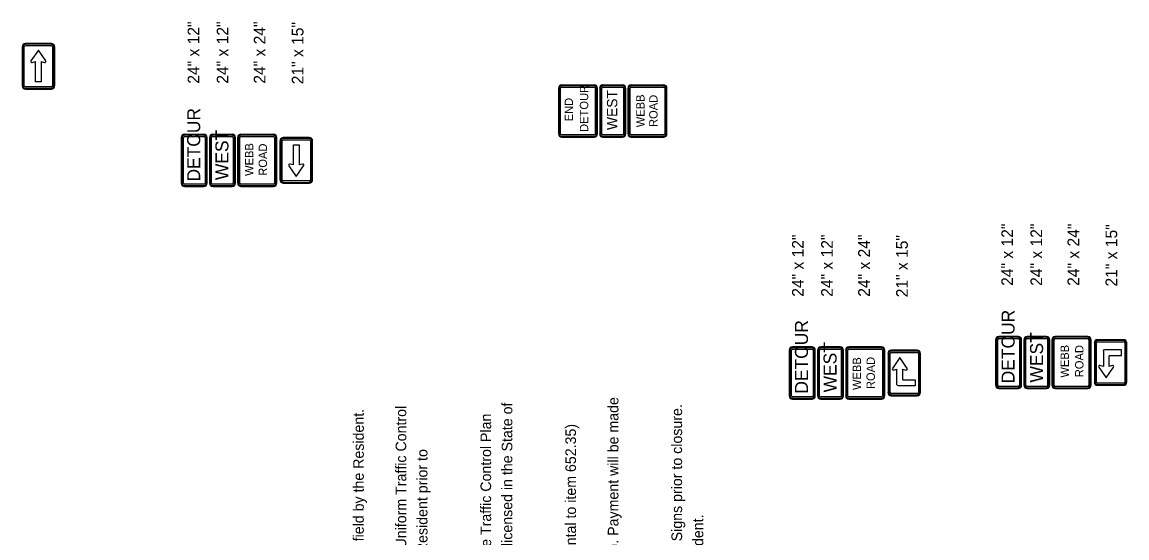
# Model space of a CAD drawing. Extents: x 1123038 to 1172987, y 554419 to 623636.
# Drawn here: x 1160796 to 1172459, y 569560 to 575008 of the extents above; entities that cross this region are included whole.
import ezdxf

# ---------------------------------------------------------------- set-up
doc = ezdxf.new("R2010")
doc.units = 0
doc.layers.add('D_Text_Standard', color=7, linetype='Continuous')
doc.layers.add('Default', color=7, linetype='Continuous')

msp = doc.modelspace()

# ---------------------------------------------------------------- linework, layer by layer
at = {"layer": 'Default'}
for p, q in [((1161105, 574782), (1160830, 574782)), ((1161105, 574773), (1160830, 574773)), ((1160830, 574759), (1161105, 574759)), ((1160796, 574747), (1160796, 574335)), ((1160804, 574747), (1160804, 574335)), ((1160819, 574335), (1160819, 574747)), ((1160968, 574713), (1160889, 574599)), ((1161046, 574599), (1160968, 574713)), ((1161117, 574747), (1161117, 574335)), ((1161131, 574335), (1161131, 574747)), ((1161140, 574335), (1161140, 574747)), ((1160901, 574581), (1160938, 574590)), ((1160938, 574378), (1160938, 574590)), ((1160998, 574590), (1161034, 574581)), ((1160998, 574590), (1160998, 574378)), ((1161105, 574323), (1160830, 574323)), ((1160830, 574309), (1161105, 574309)), ((1160830, 574300), (1161105, 574300)), ((1160998, 574378), (1160938, 574378)), ((1166457, 574309), (1166457, 573827)), ((1166466, 574309), (1166466, 573827)), ((1166480, 573827), (1166480, 574309)), ((1166836, 574343), (1166492, 574343)), ((1166836, 574334), (1166492, 574334)), ((1166492, 574320), (1166836, 574320)), ((1166847, 574309), (1166847, 573827)), ((1166861, 573827), (1166861, 574309)), ((1166870, 573827), (1166870, 574309)), ((1166893, 574309), (1166893, 573827)), ((1166901, 574309), (1166901, 573827)), ((1166916, 573827), (1166916, 574309)), ((1167133, 574343), (1166927, 574343)), ((1167133, 574334), (1166927, 574334)), ((1166927, 574320), (1167133, 574320)), ((1167145, 574309), (1167145, 573827)), ((1167159, 573827), (1167159, 574309)), ((1167168, 573827), (1167168, 574309)), ((1167191, 574309), (1167191, 573827)), ((1167199, 574309), (1167199, 573827)), ((1167214, 573827), (1167214, 574309)), ((1167569, 574343), (1167225, 574343)), ((1167569, 574334), (1167225, 574334)), ((1167225, 574320), (1167569, 574320)), ((1167580, 574309), (1167580, 573827)), ((1167595, 573827), (1167595, 574309)), ((1167603, 573827), (1167603, 574309)), ((1162716, 573822), (1162510, 573822)), ((1163014, 573822), (1162808, 573822)), ((1163449, 573822), (1163106, 573822)), ((1162475, 573788), (1162475, 573307)), ((1162484, 573788), (1162484, 573307)), ((1162498, 573307), (1162498, 573788)), ((1162716, 573814), (1162510, 573814)), ((1162510, 573800), (1162716, 573800)), ((1162728, 573788), (1162728, 573307)), ((1162742, 573307), (1162742, 573788)), ((1162750, 573307), (1162750, 573788)), ((1162773, 573788), (1162773, 573307)), ((1162782, 573788), (1162782, 573307)), ((1162796, 573307), (1162796, 573788)), ((1163014, 573814), (1162808, 573814)), ((1162808, 573800), (1163014, 573800)), ((1163025, 573788), (1163025, 573307)), ((1163040, 573307), (1163040, 573788)), ((1163048, 573307), (1163048, 573788)), ((1163071, 573788), (1163071, 573307)), ((1163080, 573788), (1163080, 573307)), ((1163094, 573307), (1163094, 573788)), ((1163449, 573814), (1163106, 573814)), ((1163106, 573800), (1163449, 573800)), ((1163461, 573788), (1163461, 573307)), ((1163475, 573307), (1163475, 573788)), ((1163484, 573307), (1163484, 573788)), ((1163518, 573754), (1163518, 573341)), ((1163527, 573754), (1163527, 573341)), ((1163541, 573341), (1163541, 573754)), ((1163828, 573788), (1163553, 573788)), ((1163828, 573779), (1163553, 573779)), ((1163553, 573765), (1163828, 573765)), ((1163660, 573711), (1163720, 573711)), ((1163660, 573499), (1163660, 573711)), ((1163720, 573711), (1163720, 573499)), ((1163839, 573754), (1163839, 573341)), ((1163853, 573341), (1163853, 573754)), ((1163862, 573341), (1163862, 573754)), ((1166836, 573816), (1166492, 573816)), ((1166492, 573802), (1166836, 573802)), ((1166492, 573793), (1166836, 573793)), ((1167133, 573816), (1166927, 573816)), ((1166927, 573802), (1167133, 573802)), ((1166927, 573793), (1167133, 573793)), ((1167569, 573816), (1167225, 573816)), ((1167225, 573802), (1167569, 573802)), ((1167225, 573793), (1167569, 573793)), ((1163612, 573490), (1163690, 573376)), ((1163660, 573499), (1163624, 573507)), ((1163690, 573376), (1163768, 573490)), ((1163756, 573507), (1163720, 573499)), ((1162716, 573295), (1162510, 573295)), ((1162510, 573281), (1162716, 573281)), ((1162510, 573272), (1162716, 573272)), ((1163014, 573295), (1162808, 573295)), ((1162808, 573281), (1163014, 573281)), ((1162808, 573272), (1163014, 573272)), ((1163449, 573295), (1163106, 573295)), ((1163106, 573281), (1163449, 573281)), ((1163106, 573272), (1163449, 573272)), ((1163828, 573330), (1163553, 573330)), ((1163553, 573315), (1163828, 573315)), ((1163553, 573307), (1163828, 573307)), ((1171072, 571653), (1171072, 571172)), ((1171081, 571653), (1171081, 571172)), ((1171095, 571172), (1171095, 571653)), ((1171313, 571687), (1171107, 571687)), ((1171313, 571679), (1171107, 571679)), ((1171107, 571665), (1171313, 571665)), ((1171324, 571653), (1171324, 571172)), ((1171339, 571172), (1171339, 571653)), ((1171347, 571172), (1171347, 571653)), ((1171370, 571653), (1171370, 571172)), ((1171379, 571653), (1171379, 571172)), ((1171393, 571172), (1171393, 571653)), ((1171611, 571687), (1171405, 571687)), ((1171611, 571679), (1171405, 571679)), ((1171405, 571665), (1171611, 571665)), ((1171622, 571653), (1171622, 571172)), ((1171637, 571172), (1171637, 571653)), ((1171645, 571172), (1171645, 571653)), ((1171668, 571653), (1171668, 571172)), ((1171677, 571653), (1171677, 571172)), ((1171691, 571172), (1171691, 571653)), ((1172046, 571687), (1171702, 571687)), ((1172046, 571679), (1171702, 571679)), ((1171702, 571665), (1172046, 571665)), ((1172058, 571653), (1172058, 571172)), ((1172072, 571172), (1172072, 571653)), ((1172081, 571172), (1172081, 571653)), ((1172115, 571619), (1172115, 571206)), ((1172124, 571619), (1172124, 571206)), ((1172138, 571206), (1172138, 571619)), ((1172424, 571653), (1172149, 571653)), ((1172424, 571645), (1172149, 571645)), ((1172149, 571630), (1172424, 571630)), ((1172436, 571619), (1172436, 571206)), ((1172450, 571206), (1172450, 571619)), ((1172459, 571206), (1172459, 571619)), ((1168894, 571542), (1168894, 571061)), ((1168903, 571542), (1168903, 571061)), ((1168917, 571061), (1168917, 571542)), ((1169135, 571577), (1168928, 571577)), ((1169135, 571568), (1168928, 571568)), ((1168928, 571554), (1169135, 571554)), ((1169146, 571542), (1169146, 571061)), ((1169160, 571061), (1169160, 571542)), ((1169169, 571061), (1169169, 571542)), ((1169192, 571542), (1169192, 571061)), ((1169200, 571542), (1169200, 571061)), ((1169215, 571061), (1169215, 571542)), ((1169433, 571577), (1169226, 571577)), ((1169433, 571568), (1169226, 571568)), ((1169226, 571554), (1169433, 571554)), ((1169444, 571542), (1169444, 571061)), ((1169458, 571061), (1169458, 571542)), ((1169467, 571061), (1169467, 571542)), ((1169490, 571542), (1169490, 571061)), ((1169498, 571542), (1169498, 571061)), ((1169513, 571061), (1169513, 571542)), ((1169868, 571577), (1169524, 571577)), ((1169868, 571568), (1169524, 571568)), ((1169524, 571554), (1169868, 571554)), ((1169879, 571542), (1169879, 571061)), ((1169894, 571061), (1169894, 571542)), ((1169902, 571061), (1169902, 571542)), ((1169937, 571508), (1169937, 571095)), ((1169945, 571508), (1169945, 571095)), ((1169960, 571095), (1169960, 571508)), ((1170246, 571542), (1169971, 571542)), ((1170246, 571534), (1169971, 571534)), ((1169971, 571519), (1170246, 571519)), ((1170258, 571508), (1170258, 571095)), ((1170272, 571095), (1170272, 571508)), ((1170280, 571095), (1170280, 571508)), ((1172210, 571533), (1172210, 571372)), ((1172403, 571546), (1172222, 571546)), ((1172278, 571486), (1172403, 571486)), ((1172403, 571486), (1172403, 571546)), ((1170061, 571465), (1169983, 571351)), ((1170140, 571351), (1170061, 571465)), ((1172210, 571372), (1172173, 571381)), ((1172270, 571372), (1172270, 571477)), ((1172306, 571381), (1172270, 571372)), ((1169995, 571333), (1170031, 571342)), ((1170031, 571181), (1170031, 571342)), ((1170091, 571342), (1170127, 571333)), ((1170091, 571342), (1170091, 571237)), ((1172161, 571363), (1172240, 571249)), ((1172240, 571249), (1172318, 571363)), ((1170225, 571168), (1170044, 571168)), ((1170100, 571229), (1170225, 571229)), ((1170225, 571229), (1170225, 571168)), ((1171313, 571160), (1171107, 571160)), ((1171107, 571146), (1171313, 571146)), ((1171107, 571137), (1171313, 571137)), ((1171611, 571160), (1171405, 571160)), ((1171405, 571146), (1171611, 571146)), ((1171405, 571137), (1171611, 571137)), ((1172046, 571160), (1171702, 571160)), ((1171702, 571146), (1172046, 571146)), ((1171702, 571137), (1172046, 571137)), ((1172424, 571195), (1172149, 571195)), ((1172149, 571180), (1172424, 571180)), ((1172149, 571172), (1172424, 571172)), ((1169135, 571050), (1168928, 571050)), ((1168928, 571035), (1169135, 571035)), ((1168928, 571027), (1169135, 571027)), ((1169433, 571050), (1169226, 571050)), ((1169226, 571035), (1169433, 571035)), ((1169226, 571027), (1169433, 571027)), ((1169868, 571050), (1169524, 571050)), ((1169524, 571035), (1169868, 571035)), ((1169524, 571027), (1169868, 571027)), ((1170246, 571084), (1169971, 571084)), ((1169971, 571070), (1170246, 571070)), ((1169971, 571061), (1170246, 571061))]:
    msp.add_line(p, q, dxfattribs=at)
for centre, radius, start, end in [((1160830, 574747), 34.4, 90, 180), ((1160830, 574747), 25.8, 90, 180), ((1160830, 574747), 11.5, 90, 180), ((1161105, 574747), 34.4, 0, 90), ((1161105, 574747), 25.8, 0, 90), ((1161105, 574747), 11.5, 0, 90), ((1160899, 574593), 11.5, 147.7244, 282.9503), ((1161036, 574593), 11.5, 257.0497, 32.2757), ((1160830, 574335), 34.4, 180, 270), ((1160830, 574335), 25.8, 180, 270), ((1160830, 574335), 11.5, 180, 270), ((1161105, 574335), 34.4, 270, 0), ((1161105, 574335), 25.8, 270, 0), ((1161105, 574335), 11.5, 270, 0), ((1166492, 574309), 34.4, 90, 180), ((1166492, 574309), 25.8, 90, 180), ((1166492, 574309), 11.5, 90, 180), ((1166836, 574309), 34.4, 0, 90), ((1166836, 574309), 25.8, 0, 90), ((1166836, 574309), 11.5, 0, 90), ((1166927, 574309), 34.4, 90, 180), ((1166927, 574309), 25.8, 90, 180), ((1166927, 574309), 11.5, 90, 180), ((1167133, 574309), 34.4, 0, 90), ((1167133, 574309), 25.8, 0, 90), ((1167133, 574309), 11.5, 0, 90), ((1167225, 574309), 34.4, 90, 180), ((1167225, 574309), 25.8, 90, 180), ((1167225, 574309), 11.5, 90, 180), ((1167569, 574309), 34.4, 0, 90), ((1167569, 574309), 25.8, 0, 90), ((1167569, 574309), 11.5, 0, 90), ((1162510, 573788), 34.4, 90, 180), ((1162716, 573788), 34.4, 0, 90), ((1162808, 573788), 34.4, 90, 180), ((1163014, 573788), 34.4, 0, 90), ((1163106, 573788), 34.4, 90, 180), ((1163449, 573788), 34.4, 0, 90), ((1166492, 573827), 34.4, 180, 270), ((1166492, 573827), 25.8, 180, 270), ((1166492, 573827), 11.5, 180, 270), ((1166836, 573827), 34.4, 270, 0), ((1166836, 573827), 25.8, 270, 0), ((1166836, 573827), 11.5, 270, 0), ((1166927, 573827), 34.4, 180, 270), ((1166927, 573827), 25.8, 180, 270), ((1166927, 573827), 11.5, 180, 270), ((1167133, 573827), 34.4, 270, 0), ((1167133, 573827), 25.8, 270, 0), ((1167133, 573827), 11.5, 270, 0), ((1167225, 573827), 34.4, 180, 270), ((1167225, 573827), 25.8, 180, 270), ((1167225, 573827), 11.5, 180, 270), ((1167569, 573827), 34.4, 270, 0), ((1167569, 573827), 25.8, 270, 0), ((1167569, 573827), 11.5, 270, 0), ((1162510, 573788), 25.8, 90, 180), ((1162510, 573788), 11.5, 90, 180), ((1162716, 573788), 25.8, 0, 90), ((1162716, 573788), 11.5, 0, 90), ((1162808, 573788), 25.8, 90, 180), ((1162808, 573788), 11.5, 90, 180), ((1163014, 573788), 25.8, 0, 90), ((1163014, 573788), 11.5, 0, 90), ((1163106, 573788), 25.8, 90, 180), ((1163106, 573788), 11.5, 90, 180), ((1163449, 573788), 25.8, 0, 90), ((1163449, 573788), 11.5, 0, 90), ((1163553, 573754), 34.4, 90, 180), ((1163553, 573754), 25.8, 90, 180), ((1163553, 573754), 11.5, 90, 180), ((1163828, 573754), 34.4, 0, 90), ((1163828, 573754), 25.8, 0, 90), ((1163828, 573754), 11.5, 0, 90), ((1163621, 573496), 11.5, 77.0497, 212.2757), ((1163759, 573496), 11.5, 327.7244, 102.9504), ((1162510, 573307), 34.4, 180, 270), ((1162510, 573307), 25.8, 180, 270), ((1162510, 573307), 11.5, 180, 270), ((1162716, 573307), 34.4, 270, 0), ((1162716, 573307), 25.8, 270, 0), ((1162716, 573307), 11.5, 270, 0), ((1162808, 573307), 34.4, 180, 270), ((1162808, 573307), 25.8, 180, 270), ((1162808, 573307), 11.5, 180, 270), ((1163014, 573307), 34.4, 270, 0), ((1163014, 573307), 25.8, 270, 0), ((1163014, 573307), 11.5, 270, 0), ((1163106, 573307), 34.4, 180, 270), ((1163106, 573307), 25.8, 180, 270), ((1163106, 573307), 11.5, 180, 270), ((1163449, 573307), 34.4, 270, 0), ((1163449, 573307), 25.8, 270, 0), ((1163449, 573307), 11.5, 270, 0), ((1163553, 573341), 34.4, 180, 270), ((1163553, 573341), 25.8, 180, 270), ((1163553, 573341), 11.5, 180, 270), ((1163828, 573341), 34.4, 270, 0), ((1163828, 573341), 25.8, 270, 0), ((1163828, 573341), 11.5, 270, 0), ((1171107, 571653), 34.4, 90, 180), ((1171107, 571653), 25.8, 90, 180), ((1171107, 571653), 11.5, 90, 180), ((1171313, 571653), 34.4, 0, 90), ((1171313, 571653), 25.8, 0, 90), ((1171313, 571653), 11.5, 0, 90), ((1171405, 571653), 34.4, 90, 180), ((1171405, 571653), 25.8, 90, 180), ((1171405, 571653), 11.5, 90, 180), ((1171611, 571653), 34.4, 0, 90), ((1171611, 571653), 25.8, 0, 90), ((1171611, 571653), 11.5, 0, 90), ((1171702, 571653), 34.4, 90, 180), ((1171702, 571653), 25.8, 90, 180), ((1171702, 571653), 11.5, 90, 180), ((1172046, 571653), 34.4, 0, 90), ((1172046, 571653), 25.8, 0, 90), ((1172046, 571653), 11.5, 0, 90), ((1172149, 571619), 34.4, 90, 180), ((1172149, 571619), 25.8, 90, 180), ((1172149, 571619), 11.5, 90, 180), ((1172424, 571619), 34.4, 0, 90), ((1172424, 571619), 25.8, 0, 90), ((1172424, 571619), 11.5, 0, 90), ((1168928, 571542), 34.4, 90, 180), ((1168928, 571542), 25.8, 90, 180), ((1168928, 571542), 11.5, 90, 180), ((1169135, 571542), 34.4, 0, 90), ((1169135, 571542), 25.8, 0, 90), ((1169135, 571542), 11.5, 0, 90), ((1169226, 571542), 34.4, 90, 180), ((1169226, 571542), 25.8, 90, 180), ((1169226, 571542), 11.5, 90, 180), ((1169433, 571542), 34.4, 0, 90), ((1169433, 571542), 25.8, 0, 90), ((1169433, 571542), 11.5, 0, 90), ((1169524, 571542), 34.4, 90, 180), ((1169524, 571542), 25.8, 90, 180), ((1169524, 571542), 11.5, 90, 180), ((1169868, 571542), 34.4, 0, 90), ((1169868, 571542), 25.8, 0, 90), ((1169868, 571542), 11.5, 0, 90), ((1169971, 571508), 34.4, 90, 180), ((1169971, 571508), 25.8, 90, 180), ((1169971, 571508), 11.5, 90, 180), ((1170246, 571508), 34.4, 0, 90), ((1170246, 571508), 25.8, 0, 90), ((1170246, 571508), 11.5, 0, 90), ((1172222, 571533), 12.9, 90, 180), ((1172278, 571477), 8.59, 90, 180), ((1172171, 571370), 11.5, 77.0497, 212.2757), ((1172308, 571370), 11.5, 327.7244, 102.9504), ((1169993, 571345), 11.5, 147.7244, 282.9503), ((1170130, 571345), 11.5, 257.0497, 32.2757), ((1170044, 571181), 12.9, 180, 270), ((1170100, 571237), 8.59, 180, 270), ((1171107, 571172), 34.4, 180, 270), ((1171107, 571172), 25.8, 180, 270), ((1171107, 571172), 11.5, 180, 270), ((1171313, 571172), 34.4, 270, 0), ((1171313, 571172), 25.8, 270, 0), ((1171313, 571172), 11.5, 270, 0), ((1171405, 571172), 34.4, 180, 270), ((1171405, 571172), 25.8, 180, 270), ((1171405, 571172), 11.5, 180, 270), ((1171611, 571172), 34.4, 270, 0), ((1171611, 571172), 25.8, 270, 0), ((1171611, 571172), 11.5, 270, 0), ((1171702, 571172), 34.4, 180, 270), ((1171702, 571172), 25.8, 180, 270), ((1171702, 571172), 11.5, 180, 270), ((1172046, 571172), 34.4, 270, 0), ((1172046, 571172), 25.8, 270, 0), ((1172046, 571172), 11.5, 270, 0), ((1172149, 571206), 34.4, 180, 270), ((1172149, 571206), 25.8, 180, 270), ((1172149, 571206), 11.5, 180, 270), ((1172424, 571206), 34.4, 270, 0), ((1172424, 571206), 25.8, 270, 0), ((1172424, 571206), 11.5, 270, 0), ((1168928, 571061), 34.4, 180, 270), ((1168928, 571061), 25.8, 180, 270), ((1168928, 571061), 11.5, 180, 270), ((1169135, 571061), 34.4, 270, 0), ((1169135, 571061), 25.8, 270, 0), ((1169135, 571061), 11.5, 270, 0), ((1169226, 571061), 34.4, 180, 270), ((1169226, 571061), 25.8, 180, 270), ((1169226, 571061), 11.5, 180, 270), ((1169433, 571061), 34.4, 270, 0), ((1169433, 571061), 25.8, 270, 0), ((1169433, 571061), 11.5, 270, 0), ((1169524, 571061), 34.4, 180, 270), ((1169524, 571061), 25.8, 180, 270), ((1169524, 571061), 11.5, 180, 270), ((1169868, 571061), 34.4, 270, 0), ((1169868, 571061), 25.8, 270, 0), ((1169868, 571061), 11.5, 270, 0), ((1169971, 571095), 34.4, 180, 270), ((1169971, 571095), 25.8, 180, 270), ((1169971, 571095), 11.5, 180, 270), ((1170246, 571095), 34.4, 270, 0), ((1170246, 571095), 25.8, 270, 0), ((1170246, 571095), 11.5, 270, 0)]:
    msp.add_arc(centre, radius, start, end, dxfattribs=at)

# ---------------------------------------------------------------- texts
at = {"layer": 'D_Text_Standard'}
for s, p in [('24" x 12"', (1162667, 574357)), ('24" x 12"', (1162974, 574357)), ('24" x 24"', (1163365, 574357)), ('21" x 15"', (1163766, 574351)), ('24" x 12"', (1171257, 572222)), ('24" x 12"', (1171564, 572222)), ('24" x 24"', (1171955, 572222)), ('21" x 15"', (1172356, 572215)), ('24" x 12"', (1169047, 572107)), ('24" x 12"', (1169354, 572107)), ('24" x 24"', (1169745, 572107)), ('21" x 15"', (1170146, 572101))]:
    msp.add_text(s, height=123.2, rotation=90, dxfattribs=at).set_placement(p)
at = {"layer": 'Default'}
for s, height, p in [('DETOUR', 88, (1166772, 573848)), ('WEST', 109.2, (1167079, 573868)), ('END', 88, (1166611, 573959)), ('WEBB', 88, (1167367, 573897)), ('ROAD', 88, (1167504, 573900)), ('DETOUR', 137.5, (1162676, 573324)), ('WEST', 137.5, (1162974, 573339)), ('WEBB', 88, (1163237, 573383)), ('ROAD', 88, (1163381, 573385)), ('DETOUR', 137.5, (1171273, 571193)), ('DETOUR', 137.5, (1169092, 571084)), ('WEST', 137.5, (1171574, 571201)), ('WEST', 137.5, (1169394, 571097)), ('WEBB', 88, (1171846, 571253)), ('ROAD', 88, (1172000, 571257)), ('WEBB', 88, (1169652, 571122)), ('ROAD', 88, (1169798, 571132)), ('5. Install 30 feet of Temporary Concrete Barrier at each end of the project (60 feet total). Payment will be made ', 112, (1167091, 563713)), ('1. All sign locations shown are approximate. Actual locations shall be determined in the field by the Resident.', 112, (1164403, 563713)), ('2. All modifications to traffic control devices shall be in accordance with the Manual on Uniform Traffic Control ', 112, (1164851, 563713)), ('submitted, Control Plan submitted, designed, and stamped by a Professional Engineer licensed in the State of ', 112, (1165971, 563713)), ('6. In addition to signs shown, the Contractor shall place Portable Changeable Message Signs prior to closure.   ', 112, (1167763, 563713)), ('3. Any and all changes and adjustments to traffic control devices shall be included in the Traffic Control Plan ', 112, (1165747, 563713)), ('4. The Contractor shall cover all existing signs that conflict with work zone signs (Incidental to item 652.35)', 112, (1166643, 563713)), ('Devices. Changes and adjustments to traffic control devices shall be approved by the Resident prior to ', 112, (1165075, 563713)), ('Locations and messages to be determined by the Contractor and approved by the Resident.', 112, (1167987, 563713))]:
    msp.add_text(s, height=height, rotation=90, dxfattribs=at).set_placement(p)

doc.saveas('drawing.dxf')
